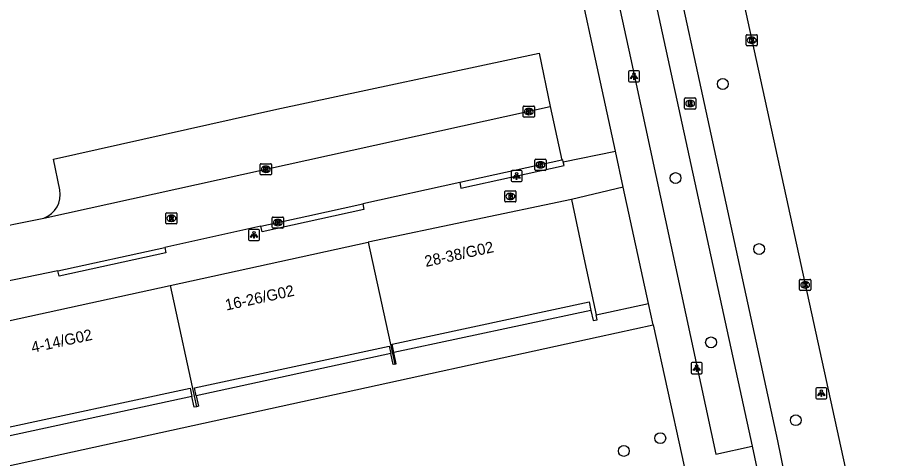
# Model space of a CAD drawing. Extents: x 160037 to 160839, y 385326 to 386441.
# Drawn here: x 160701.6 to 160780.4, y 385634.1 to 385673.7 of the extents above; entities that cross this region are included whole.
import ezdxf

# ---------------------------------------------------------------- set-up
doc = ezdxf.new("R2010")
doc.units = 0
for name, color, linetype in [('IMGEO_Boom', 7, 'Continuous'), ('IMGEO_Brandkraan', 7, 'Continuous'), ('IMGEO_Fietspad_gesloten', 7, 'Continuous'), ('IMGEO_Kolk', 7, 'Continuous'), ('IMGEO_Lichtpunt', 7, 'Continuous'), ('IMGEO_Pand', 7, 'Continuous'), ('IMGEO_Pand_nummerreeks', 7, 'Continuous'), ('IMGEO_Parkeervlak_open', 7, 'Continuous'), ('IMGEO_Rijbaan_lokaal_gesloten', 7, 'Continuous'), ('IMGEO_Rijbaan_lokaal_open', 7, 'Continuous'), ('IMGEO_Rioolput', 7, 'Continuous'), ('IMGEO_Voetpad_open', 7, 'Continuous')]:
    doc.layers.add(name, color=color, linetype=linetype)

msp = doc.modelspace()

# ---------------------------------------------------------------- linework, layer by layer
at = {"layer": 'IMGEO_Boom'}
for centre in [(160765.029, 385667.771), (160760.781, 385659.317), (160768.297, 385652.933), (160763.972, 385644.549), (160771.592, 385637.553), (160759.411, 385635.938), (160756.133, 385634.788)]:
    msp.add_circle(centre, 0.489, dxfattribs=at)
at = {"layer": 'IMGEO_Brandkraan'}
for p, q in [((160745.433, 385657.246), (160745.433, 385658.098)), ((160745.508, 385658.172), (160746.36, 385658.172)), ((160745.921, 385657.952), (160745.946, 385657.952)), ((160746.434, 385658.098), (160746.434, 385657.246)), ((160746.36, 385657.172), (160745.508, 385657.172)), ((160745.944, 385657.392), (160745.919, 385657.392))]:
    msp.add_line(p, q, dxfattribs=at)
for points in [[(160745.433, 385657.246), (160745.433, 385658.098)], [(160745.508, 385658.172), (160746.36, 385658.172)], [(160746.434, 385658.098), (160746.434, 385657.246)], [(160746.36, 385657.172), (160745.508, 385657.172)], [(160745.781, 385657.872), (160745.781, 385657.472), (160745.994, 385657.472)], [(160746.012, 385657.872), (160745.781, 385657.872)], [(160745.96, 385657.791), (160745.906, 385657.791), (160745.906, 385657.715)], [(160745.906, 385657.715), (160745.959, 385657.715)], [(160745.968, 385657.639), (160745.906, 385657.639), (160745.906, 385657.558)], [(160745.906, 385657.558), (160745.968, 385657.558)]]:
    msp.add_lwpolyline(points, dxfattribs=at)
for centre, radius, start, end in [((160745.51, 385658.096), 0.0765, 91.55205, 178.44795), ((160745.51, 385658.096), 0.0765, 91.55205, 178.44795), ((160746.358, 385658.096), 0.0765, 1.55205, 88.44795), ((160746.358, 385658.096), 0.0765, 1.55205, 88.44795), ((160745.51, 385657.248), 0.0765, 181.55205, 268.44795), ((160745.51, 385657.248), 0.0765, 181.55205, 268.44795), ((160745.961, 385657.753), 0.0379, 267.82845, 90.93552), ((160745.969, 385657.598), 0.0404, 269.87594, 90.50774), ((160746, 385657.723), 0.251, 268.66757, 293.53466), ((160746.016, 385657.727), 0.145, 59.4692, 91.53667), ((160746.041, 385657.774), 0.0922, 285.51372, 58.15012), ((160746.046, 385657.582), 0.105, 301.31148, 78.98903), ((160746.358, 385657.248), 0.0765, 271.55205, 358.44795), ((160746.358, 385657.248), 0.0765, 271.55205, 358.44795)]:
    msp.add_arc(centre, radius, start, end, dxfattribs=at)
for centre, major_axis, ratio, start_param, end_param in [((160745.92, 385657.672), (-0.387, 0.002), 0.722429, 4.712389, 7.853982), ((160745.945, 385657.672), (-0.39, 0.002), 0.717154, 1.570796, 4.712389)]:
    msp.add_ellipse(centre, major_axis=major_axis, ratio=ratio, start_param=start_param, end_param=end_param, dxfattribs=at)
at = {"layer": 'IMGEO_Fietspad_gesloten'}
for points in [[(160750.418, 385714.749), (160750.95, 385712.317), (160752.149, 385706.509), (160767.671, 385635.207)], [(160775.044, 385612.131), (160775.03, 385612.19), (160770.584, 385632.759), (160769.982, 385635.685), (160754.19, 385708.351), (160753.59, 385711.343), (160752.714, 385715.259)], [(160767.671, 385635.207), (160768.306, 385632.258)]]:
    msp.add_lwpolyline(points, dxfattribs=at)
at = {"layer": 'IMGEO_Kolk'}
for p, q in [((160767.133, 385671.277), (160767.133, 385672.129)), ((160767.208, 385672.203), (160768.06, 385672.203)), ((160768.134, 385672.129), (160768.134, 385671.277)), ((160767.644, 385671.423), (160767.619, 385671.423)), ((160767.621, 385671.983), (160767.646, 385671.983)), ((160768.06, 385671.203), (160767.208, 385671.203)), ((160747.164, 385665.79), (160748.016, 385665.79)), ((160747.089, 385664.864), (160747.089, 385665.716)), ((160747.6, 385665.01), (160747.575, 385665.01)), ((160747.577, 385665.57), (160747.602, 385665.57)), ((160748.09, 385665.716), (160748.09, 385664.864)), ((160748.016, 385664.79), (160747.164, 385664.79)), ((160723.445, 385659.678), (160723.445, 385660.53)), ((160723.52, 385660.604), (160724.372, 385660.604)), ((160723.933, 385660.384), (160723.958, 385660.384)), ((160724.446, 385660.53), (160724.446, 385659.678)), ((160748.142, 385660.083), (160748.142, 385660.935)), ((160748.217, 385661.009), (160749.069, 385661.009)), ((160748.63, 385660.789), (160748.655, 385660.789)), ((160749.143, 385660.935), (160749.143, 385660.083)), ((160724.372, 385659.604), (160723.52, 385659.604)), ((160723.956, 385659.824), (160723.931, 385659.824)), ((160749.069, 385660.009), (160748.217, 385660.009)), ((160748.653, 385660.229), (160748.628, 385660.229)), ((160724.526, 385654.888), (160724.526, 385655.74)), ((160724.601, 385655.814), (160725.453, 385655.814)), ((160725.014, 385655.594), (160725.039, 385655.594)), ((160725.527, 385655.74), (160725.527, 385654.888)), ((160725.453, 385654.814), (160724.601, 385654.814)), ((160725.037, 385655.034), (160725.012, 385655.034)), ((160771.937, 385649.286), (160771.937, 385650.138)), ((160772.012, 385650.212), (160772.864, 385650.212)), ((160772.938, 385650.138), (160772.938, 385649.286)), ((160772.448, 385649.432), (160772.423, 385649.432)), ((160772.425, 385649.992), (160772.45, 385649.992)), ((160772.864, 385649.212), (160772.012, 385649.212))]:
    msp.add_line(p, q, dxfattribs=at)
for points in [[(160767.133, 385671.277), (160767.133, 385672.129)], [(160767.208, 385672.203), (160768.06, 385672.203)], [(160768.134, 385672.129), (160768.134, 385671.277)], [(160767.454, 385671.903), (160767.577, 385671.903), (160767.577, 385671.752), (160767.707, 385671.903), (160767.871, 385671.903), (160767.725, 385671.752), (160767.878, 385671.503), (160767.726, 385671.503), (160767.641, 385671.667), (160767.577, 385671.6), (160767.577, 385671.503), (160767.454, 385671.503), (160767.454, 385671.903)], [(160768.06, 385671.203), (160767.208, 385671.203)], [(160747.164, 385665.79), (160748.016, 385665.79)], [(160747.089, 385664.864), (160747.089, 385665.716)], [(160747.41, 385665.49), (160747.533, 385665.49), (160747.533, 385665.339), (160747.663, 385665.49), (160747.827, 385665.49), (160747.681, 385665.339), (160747.834, 385665.09), (160747.682, 385665.09), (160747.597, 385665.254), (160747.533, 385665.187), (160747.533, 385665.09), (160747.41, 385665.09), (160747.41, 385665.49)], [(160748.09, 385665.716), (160748.09, 385664.864)], [(160748.016, 385664.79), (160747.164, 385664.79)], [(160723.445, 385659.678), (160723.445, 385660.53)], [(160723.52, 385660.604), (160724.372, 385660.604)], [(160723.766, 385660.304), (160723.889, 385660.304), (160723.889, 385660.153), (160724.019, 385660.304), (160724.183, 385660.304), (160724.037, 385660.153), (160724.19, 385659.904), (160724.038, 385659.904), (160723.953, 385660.068), (160723.889, 385660.001), (160723.889, 385659.904), (160723.766, 385659.904), (160723.766, 385660.304)], [(160724.446, 385660.53), (160724.446, 385659.678)], [(160748.142, 385660.083), (160748.142, 385660.935)], [(160748.217, 385661.009), (160749.069, 385661.009)], [(160748.463, 385660.709), (160748.586, 385660.709), (160748.586, 385660.558), (160748.716, 385660.709), (160748.88, 385660.709), (160748.734, 385660.558), (160748.887, 385660.309), (160748.735, 385660.309), (160748.65, 385660.473), (160748.586, 385660.406), (160748.586, 385660.309), (160748.463, 385660.309), (160748.463, 385660.709)], [(160749.143, 385660.935), (160749.143, 385660.083)], [(160724.372, 385659.604), (160723.52, 385659.604)], [(160749.069, 385660.009), (160748.217, 385660.009)], [(160724.526, 385654.888), (160724.526, 385655.74)], [(160724.601, 385655.814), (160725.453, 385655.814)], [(160725.527, 385655.74), (160725.527, 385654.888)], [(160725.453, 385654.814), (160724.601, 385654.814)], [(160724.847, 385655.514), (160724.97, 385655.514), (160724.97, 385655.363), (160725.1, 385655.514), (160725.264, 385655.514), (160725.118, 385655.363), (160725.271, 385655.114), (160725.119, 385655.114), (160725.034, 385655.278), (160724.97, 385655.211), (160724.97, 385655.114), (160724.847, 385655.114), (160724.847, 385655.514)], [(160771.937, 385649.286), (160771.937, 385650.138)], [(160772.012, 385650.212), (160772.864, 385650.212)], [(160772.938, 385650.138), (160772.938, 385649.286)], [(160772.258, 385649.912), (160772.381, 385649.912), (160772.381, 385649.761), (160772.511, 385649.912), (160772.675, 385649.912), (160772.529, 385649.761), (160772.682, 385649.512), (160772.53, 385649.512), (160772.445, 385649.676), (160772.381, 385649.609), (160772.381, 385649.512), (160772.258, 385649.512), (160772.258, 385649.912)], [(160772.864, 385649.212), (160772.012, 385649.212)]]:
    msp.add_lwpolyline(points, dxfattribs=at)
for centre, start, end in [((160767.21, 385672.127), 91.55205, 178.44795), ((160767.21, 385672.127), 91.55205, 178.44795), ((160768.058, 385672.127), 1.55205, 88.44795), ((160768.058, 385672.127), 1.55205, 88.44795), ((160767.21, 385671.279), 181.55205, 268.44795), ((160767.21, 385671.279), 181.55205, 268.44795), ((160768.058, 385671.279), 271.55205, 358.44795), ((160768.058, 385671.279), 271.55205, 358.44795), ((160747.166, 385665.714), 91.55205, 178.44795), ((160747.166, 385665.714), 91.55205, 178.44795), ((160748.014, 385665.714), 1.55205, 88.44795), ((160748.014, 385665.714), 1.55205, 88.44795), ((160747.166, 385664.866), 181.55205, 268.44795), ((160747.166, 385664.866), 181.55205, 268.44795), ((160748.014, 385664.866), 271.55205, 358.44795), ((160748.014, 385664.866), 271.55205, 358.44795), ((160723.522, 385660.528), 91.55205, 178.44795), ((160723.522, 385660.528), 91.55205, 178.44795), ((160724.37, 385660.528), 1.55205, 88.44795), ((160724.37, 385660.528), 1.55205, 88.44795), ((160748.219, 385660.933), 91.55205, 178.44795), ((160748.219, 385660.933), 91.55205, 178.44795), ((160749.067, 385660.933), 1.55205, 88.44795), ((160749.067, 385660.933), 1.55205, 88.44795), ((160723.522, 385659.68), 181.55205, 268.44795), ((160723.522, 385659.68), 181.55205, 268.44795), ((160724.37, 385659.68), 271.55205, 358.44795), ((160724.37, 385659.68), 271.55205, 358.44795), ((160748.219, 385660.085), 181.55205, 268.44795), ((160748.219, 385660.085), 181.55205, 268.44795), ((160749.067, 385660.085), 271.55205, 358.44795), ((160749.067, 385660.085), 271.55205, 358.44795), ((160724.603, 385655.738), 91.55205, 178.44795), ((160724.603, 385655.738), 91.55205, 178.44795), ((160725.451, 385655.738), 1.55205, 88.44795), ((160725.451, 385655.738), 1.55205, 88.44795), ((160724.603, 385654.89), 181.55205, 268.44795), ((160724.603, 385654.89), 181.55205, 268.44795), ((160725.451, 385654.89), 271.55205, 358.44795), ((160725.451, 385654.89), 271.55205, 358.44795), ((160772.014, 385650.136), 91.55205, 178.44795), ((160772.014, 385650.136), 91.55205, 178.44795), ((160772.862, 385650.136), 1.55205, 88.44795), ((160772.862, 385650.136), 1.55205, 88.44795), ((160772.014, 385649.288), 181.55205, 268.44795), ((160772.014, 385649.288), 181.55205, 268.44795), ((160772.862, 385649.288), 271.55205, 358.44795), ((160772.862, 385649.288), 271.55205, 358.44795)]:
    msp.add_arc(centre, 0.0765, start, end, dxfattribs=at)
for centre, major_axis, ratio, start_param, end_param in [((160767.62, 385671.703), (-0.387, 0.002), 0.722429, 4.712389, 7.853982), ((160767.645, 385671.703), (-0.39, 0.002), 0.717154, 1.570796, 4.712389), ((160747.576, 385665.29), (-0.387, 0.002), 0.722429, 4.712389, 7.853982), ((160747.601, 385665.29), (-0.39, 0.002), 0.717154, 1.570796, 4.712389), ((160723.932, 385660.104), (-0.387, 0.002), 0.722429, 4.712389, 7.853982), ((160723.957, 385660.104), (-0.39, 0.002), 0.717154, 1.570796, 4.712389), ((160748.629, 385660.509), (-0.387, 0.002), 0.722429, 4.712389, 7.853982), ((160748.654, 385660.509), (-0.39, 0.002), 0.717154, 1.570796, 4.712389), ((160725.013, 385655.314), (-0.387, 0.002), 0.722429, 4.712389, 7.853982), ((160725.038, 385655.314), (-0.39, 0.002), 0.717154, 1.570796, 4.712389), ((160772.424, 385649.712), (-0.387, 0.002), 0.722429, 4.712389, 7.853982), ((160772.449, 385649.712), (-0.39, 0.002), 0.717154, 1.570796, 4.712389)]:
    msp.add_ellipse(centre, major_axis=major_axis, ratio=ratio, start_param=start_param, end_param=end_param, dxfattribs=at)
at = {"layer": 'IMGEO_Lichtpunt'}
for p, q in [((160757.443, 385668.959), (160756.635, 385668.959)), ((160757.443, 385668.959), (160756.635, 385668.959)), ((160756.541, 385668.864), (160756.541, 385668.057)), ((160756.541, 385668.864), (160756.541, 385668.057)), ((160757.537, 385668.057), (160757.537, 385668.864)), ((160757.537, 385668.057), (160757.537, 385668.864)), ((160756.635, 385667.963), (160757.443, 385667.963)), ((160756.635, 385667.963), (160757.443, 385667.963)), ((160745.992, 385659.906), (160745.992, 385659.099)), ((160745.992, 385659.906), (160745.992, 385659.099)), ((160746.894, 385660.001), (160746.086, 385660.001)), ((160746.894, 385660.001), (160746.086, 385660.001)), ((160746.988, 385659.099), (160746.988, 385659.906)), ((160746.988, 385659.099), (160746.988, 385659.906)), ((160746.086, 385659.005), (160746.894, 385659.005)), ((160746.086, 385659.005), (160746.894, 385659.005)), ((160722.386, 385654.609), (160722.386, 385653.802)), ((160722.386, 385654.609), (160722.386, 385653.802)), ((160723.288, 385654.704), (160722.48, 385654.704)), ((160723.288, 385654.704), (160722.48, 385654.704)), ((160723.382, 385653.802), (160723.382, 385654.609)), ((160723.382, 385653.802), (160723.382, 385654.609)), ((160722.48, 385653.708), (160723.288, 385653.708)), ((160722.48, 385653.708), (160723.288, 385653.708)), ((160762.191, 385642.635), (160762.191, 385641.828)), ((160762.191, 385642.635), (160762.191, 385641.828)), ((160763.093, 385642.73), (160762.285, 385642.73)), ((160763.093, 385642.73), (160762.285, 385642.73)), ((160763.187, 385641.828), (160763.187, 385642.635)), ((160763.187, 385641.828), (160763.187, 385642.635)), ((160762.285, 385641.734), (160763.093, 385641.734)), ((160762.285, 385641.734), (160763.093, 385641.734)), ((160773.392, 385640.377), (160773.392, 385639.57)), ((160773.392, 385640.377), (160773.392, 385639.57)), ((160774.294, 385640.472), (160773.486, 385640.472)), ((160774.294, 385640.472), (160773.486, 385640.472)), ((160774.388, 385639.57), (160774.388, 385640.377)), ((160774.388, 385639.57), (160774.388, 385640.377)), ((160773.486, 385639.476), (160774.294, 385639.476)), ((160773.486, 385639.476), (160774.294, 385639.476))]:
    msp.add_line(p, q, dxfattribs=at)
for points in [[(160756.915, 385668.528), (160756.954, 385668.5), (160756.766, 385668.238), (160756.728, 385668.265), (160756.915, 385668.528)], [(160757.017, 385668.48), (160757.064, 385668.48), (160757.064, 385668.158), (160757.017, 385668.158), (160757.017, 385668.48)], [(160757.127, 385668.5), (160757.165, 385668.527), (160757.352, 385668.265), (160757.313, 385668.237), (160757.127, 385668.5)], [(160746.366, 385659.57), (160746.405, 385659.542), (160746.217, 385659.28), (160746.179, 385659.307), (160746.366, 385659.57)], [(160746.468, 385659.522), (160746.515, 385659.522), (160746.515, 385659.2), (160746.468, 385659.2), (160746.468, 385659.522)], [(160746.578, 385659.542), (160746.616, 385659.569), (160746.803, 385659.307), (160746.764, 385659.279), (160746.578, 385659.542)], [(160722.76, 385654.273), (160722.799, 385654.245), (160722.611, 385653.983), (160722.573, 385654.01), (160722.76, 385654.273)], [(160722.862, 385654.225), (160722.909, 385654.225), (160722.909, 385653.903), (160722.862, 385653.903), (160722.862, 385654.225)], [(160722.972, 385654.245), (160723.01, 385654.272), (160723.197, 385654.01), (160723.158, 385653.982), (160722.972, 385654.245)], [(160762.565, 385642.299), (160762.604, 385642.271), (160762.416, 385642.009), (160762.378, 385642.036), (160762.565, 385642.299)], [(160762.667, 385642.251), (160762.714, 385642.251), (160762.714, 385641.929), (160762.667, 385641.929), (160762.667, 385642.251)], [(160762.777, 385642.271), (160762.815, 385642.298), (160763.002, 385642.036), (160762.963, 385642.008), (160762.777, 385642.271)], [(160773.766, 385640.041), (160773.805, 385640.013), (160773.617, 385639.751), (160773.579, 385639.778), (160773.766, 385640.041)], [(160773.868, 385639.993), (160773.915, 385639.993), (160773.915, 385639.671), (160773.868, 385639.671), (160773.868, 385639.993)], [(160773.978, 385640.013), (160774.016, 385640.04), (160774.203, 385639.778), (160774.164, 385639.75), (160773.978, 385640.013)]]:
    msp.add_lwpolyline(points, dxfattribs=at)
for centre in [(160757.04, 385668.662), (160746.491, 385659.704), (160722.885, 385654.407), (160762.69, 385642.433), (160773.891, 385640.175)]:
    msp.add_circle(centre, 0.0994, dxfattribs=at)
for centre, start, end in [((160756.635, 385668.864), 90, 180), ((160756.635, 385668.864), 90, 180), ((160757.443, 385668.864), 0, 90), ((160757.443, 385668.864), 0, 90), ((160756.635, 385668.057), 180, 270), ((160756.635, 385668.057), 180, 270), ((160757.443, 385668.057), 270, 0), ((160757.443, 385668.057), 270, 360), ((160746.086, 385659.906), 90, 180), ((160746.086, 385659.906), 90, 180), ((160746.894, 385659.906), 0, 90), ((160746.894, 385659.906), 0, 90), ((160746.086, 385659.099), 180, 270), ((160746.086, 385659.099), 180, 270), ((160746.894, 385659.099), 270, 0), ((160746.894, 385659.099), 270, 360), ((160722.48, 385654.609), 90, 180), ((160722.48, 385654.609), 90, 180), ((160723.288, 385654.609), 0, 90), ((160723.288, 385654.609), 0, 90), ((160722.48, 385653.802), 180, 270), ((160722.48, 385653.802), 180, 270), ((160723.288, 385653.802), 270, 0), ((160723.288, 385653.802), 270, 360), ((160762.285, 385642.635), 90, 180), ((160762.285, 385642.635), 90, 180), ((160763.093, 385642.635), 0, 90), ((160763.093, 385642.635), 0, 90), ((160762.285, 385641.828), 180, 270), ((160762.285, 385641.828), 180, 270), ((160763.093, 385641.828), 270, 0), ((160763.093, 385641.828), 270, 360), ((160773.486, 385640.377), 90, 180), ((160773.486, 385640.377), 90, 180), ((160774.294, 385640.377), 0, 90), ((160774.294, 385640.377), 0, 90), ((160773.486, 385639.57), 180, 270), ((160773.486, 385639.57), 180, 270), ((160774.294, 385639.57), 270, 0), ((160774.294, 385639.57), 270, 360)]:
    msp.add_arc(centre, 0.0946, start, end, dxfattribs=at)
at = {"layer": 'IMGEO_Pand'}
for points in [[(160751.417, 385657.403), (160733.147, 385653.545)], [(160751.417, 385657.403), (160752.546, 385652.138), (160753.642, 385647.02)], [(160715.356, 385649.66), (160733.147, 385653.545)], [(160733.147, 385653.545), (160735.537, 385642.603)], [(160697.201, 385645.695), (160715.356, 385649.66)], [(160715.356, 385649.66), (160717.701, 385638.764)], [(160735.465, 385643.624), (160735.302, 385644.385), (160753.015, 385648.181), (160753.176, 385647.428)], [(160753.176, 385647.428), (160753.373, 385646.51), (160753.735, 385646.588), (160753.642, 385647.02)], [(160717.698, 385639.74), (160717.543, 385640.463), (160735.044, 385644.214), (160735.186, 385643.554)], [(160735.537, 385642.603), (160735.396, 385642.573), (160735.186, 385643.554)], [(160735.537, 385642.603), (160735.677, 385642.633), (160735.465, 385643.624)], [(160699.679, 385635.881), (160699.514, 385636.649), (160717.138, 385640.427), (160717.295, 385639.695)], [(160717.701, 385638.764), (160717.503, 385638.722), (160717.295, 385639.695)], [(160717.698, 385639.74), (160717.898, 385638.806), (160717.701, 385638.764)]]:
    msp.add_lwpolyline(points, dxfattribs=at)
at = {"layer": 'IMGEO_Parkeervlak_open'}
msp.add_lwpolyline([(160705.42, 385658.254), (160704.845, 385661.028), (160724.924, 385665.504), (160748.512, 385670.542), (160749.509, 385665.757)], dxfattribs=at)
msp.add_arc((160703.261, 385657.808), 2.205, 289.01256, 11.67825, dxfattribs=at)
at = {"layer": 'IMGEO_Rijbaan_lokaal_gesloten'}
msp.add_lwpolyline([(160757.948, 385716.034), (160779.653, 385616.692), (160780.375, 385613.325)], dxfattribs=at)
at = {"layer": 'IMGEO_Rijbaan_lokaal_open'}
for points in [[(160703.979, 385655.723), (160749.509, 385665.757)], [(160749.509, 385665.757), (160750.548, 385660.927)], [(160750.548, 385660.927), (160741.382, 385658.91)], [(160741.382, 385658.91), (160732.657, 385656.99)], [(160723.506, 385654.979), (160727.646, 385655.887), (160732.657, 385656.99)], [(160697.696, 385654.461), (160698.29, 385654.583), (160703.979, 385655.723)], [(160723.506, 385654.979), (160714.858, 385653.082)], [(160705.261, 385650.98), (160714.858, 385653.082)], [(160705.261, 385650.98), (160699.553, 385649.804), (160698.918, 385649.662)]]:
    msp.add_lwpolyline(points, dxfattribs=at)
at = {"layer": 'IMGEO_Rioolput'}
for p, q in [((160761.593, 385665.591), (160761.593, 385666.443)), ((160761.668, 385666.517), (160762.52, 385666.517)), ((160762.081, 385666.297), (160762.106, 385666.297)), ((160762.594, 385666.443), (160762.594, 385665.591)), ((160762.52, 385665.517), (160761.668, 385665.517)), ((160762.104, 385665.737), (160762.079, 385665.737)), ((160714.958, 385655.272), (160714.958, 385656.124)), ((160715.033, 385656.198), (160715.885, 385656.198)), ((160715.446, 385655.978), (160715.471, 385655.978)), ((160715.959, 385656.124), (160715.959, 385655.272)), ((160715.885, 385655.198), (160715.033, 385655.198)), ((160715.469, 385655.418), (160715.444, 385655.418))]:
    msp.add_line(p, q, dxfattribs=at)
for points in [[(160761.593, 385665.591), (160761.593, 385666.443)], [(160761.668, 385666.517), (160762.52, 385666.517)], [(160762.182, 385666.215), (160761.93, 385666.217), (160761.93, 385665.817)], [(160761.93, 385665.817), (160762.054, 385665.817), (160762.054, 385665.979), (160762.065, 385665.979)], [(160762.108, 385666.136), (160762.054, 385666.136), (160762.054, 385666.055)], [(160762.054, 385666.055), (160762.106, 385666.055)], [(160762.112, 385665.95), (160762.183, 385665.817), (160762.323, 385665.817), (160762.258, 385665.943)], [(160762.594, 385666.443), (160762.594, 385665.591)], [(160762.52, 385665.517), (160761.668, 385665.517)], [(160714.958, 385655.272), (160714.958, 385656.124)], [(160715.033, 385656.198), (160715.885, 385656.198)], [(160715.547, 385655.896), (160715.295, 385655.898), (160715.295, 385655.498)], [(160715.295, 385655.498), (160715.419, 385655.498), (160715.419, 385655.66), (160715.43, 385655.66)], [(160715.473, 385655.817), (160715.419, 385655.817), (160715.419, 385655.736)], [(160715.419, 385655.736), (160715.471, 385655.736)], [(160715.477, 385655.631), (160715.548, 385655.498), (160715.688, 385655.498), (160715.623, 385655.624)], [(160715.959, 385656.124), (160715.959, 385655.272)], [(160715.885, 385655.198), (160715.033, 385655.198)]]:
    msp.add_lwpolyline(points, dxfattribs=at)
for centre, radius, start, end in [((160761.67, 385666.441), 0.0765, 91.55205, 178.44795), ((160761.67, 385666.441), 0.0765, 91.55205, 178.44795), ((160762.064, 385665.926), 0.0533, 26.02933, 88.69889), ((160762.09, 385666.244), 0.19, 274.7715, 282.96867), ((160762.114, 385666.04), 0.0964, 77.00612, 93.18647), ((160762.128, 385666.097), 0.0378, 276.66336, 79.67722), ((160762.181, 385666.105), 0.109, 350.36119, 89.41601), ((160762.179, 385666.105), 0.112, 277.58423, 350.98172), ((160762.163, 385665.89), 0.108, 29.51342, 73.79051), ((160762.518, 385666.441), 0.0765, 1.55205, 88.44795), ((160762.518, 385666.441), 0.0765, 1.55205, 88.44795), ((160761.67, 385665.593), 0.0765, 181.55205, 268.44795), ((160761.67, 385665.593), 0.0765, 181.55205, 268.44795), ((160762.518, 385665.593), 0.0765, 271.55205, 358.44795), ((160762.518, 385665.593), 0.0765, 271.55205, 358.44795), ((160715.035, 385656.122), 0.0765, 91.55205, 178.44795), ((160715.035, 385656.122), 0.0765, 91.55205, 178.44795), ((160715.429, 385655.607), 0.0533, 26.02933, 88.69889), ((160715.455, 385655.925), 0.19, 274.7715, 282.96867), ((160715.479, 385655.721), 0.0964, 77.00612, 93.18647), ((160715.493, 385655.778), 0.0378, 276.66336, 79.67722), ((160715.546, 385655.786), 0.109, 350.36119, 89.41601), ((160715.544, 385655.786), 0.112, 277.58423, 350.98172), ((160715.528, 385655.571), 0.108, 29.51342, 73.79051), ((160715.883, 385656.122), 0.0765, 1.55205, 88.44795), ((160715.883, 385656.122), 0.0765, 1.55205, 88.44795), ((160715.035, 385655.274), 0.0765, 181.55205, 268.44795), ((160715.035, 385655.274), 0.0765, 181.55205, 268.44795), ((160715.883, 385655.274), 0.0765, 271.55205, 358.44795), ((160715.883, 385655.274), 0.0765, 271.55205, 358.44795)]:
    msp.add_arc(centre, radius, start, end, dxfattribs=at)
for centre, major_axis, ratio, start_param, end_param in [((160762.08, 385666.017), (-0.387, 0.002), 0.722429, 4.712389, 7.853982), ((160762.105, 385666.017), (-0.39, 0.002), 0.717154, 1.570796, 4.712389), ((160715.445, 385655.698), (-0.387, 0.002), 0.722429, 4.712389, 7.853982), ((160715.47, 385655.698), (-0.39, 0.002), 0.717154, 1.570796, 4.712389)]:
    msp.add_ellipse(centre, major_axis=major_axis, ratio=ratio, start_param=start_param, end_param=end_param, dxfattribs=at)
at = {"layer": 'IMGEO_Voetpad_open'}
for points in [[(160750.418, 385714.749), (160747.106, 385714.042), (160747.585, 385711.838), (160748.912, 385705.94), (160756.742, 385670.124), (160764.406, 385634.512), (160767.671, 385635.207)], [(160755.372, 385661.736), (160750.486, 385684.225), (160749.841, 385687.196)], [(160750.687, 385660.776), (160755.372, 385661.736)], [(160756.08, 385658.496), (160755.372, 385661.736)], [(160741.382, 385658.91), (160741.486, 385658.421), (160750.762, 385660.439), (160750.687, 385660.776)], [(160750.687, 385660.776), (160750.648, 385660.947), (160750.548, 385660.927)], [(160756.08, 385658.496), (160751.417, 385657.403)], [(160758.358, 385648.049), (160756.08, 385658.496)], [(160732.657, 385656.99), (160732.765, 385656.482), (160723.61, 385654.49), (160723.506, 385654.979)], [(160714.858, 385653.082), (160714.962, 385652.593), (160705.362, 385650.504), (160705.261, 385650.98)], [(160753.642, 385647.02), (160758.358, 385648.049)], [(160758.778, 385646.124), (160758.358, 385648.049)], [(160753.176, 385647.428), (160735.465, 385643.624)], [(160696.668, 385632.545), (160727.249, 385639.24), (160753.839, 385645.047), (160758.778, 385646.124)], [(160758.778, 385646.124), (160761.339, 385634.379), (160763.908, 385622.573)], [(160735.186, 385643.554), (160717.698, 385639.74)], [(160717.295, 385639.695), (160699.679, 385635.881)]]:
    msp.add_lwpolyline(points, dxfattribs=at)

# ---------------------------------------------------------------- texts
at = {"layer": 'IMGEO_Pand_nummerreeks'}
for s, p in [('28-38/G02', (160738.335, 385651.321)), ('16-26/G02', (160720.404, 385647.405)), ('4-14/G02', (160702.97, 385643.598))]:
    msp.add_text(s, height=1, rotation=12.31906, dxfattribs=at).set_placement(p)

doc.saveas('drawing.dxf')
